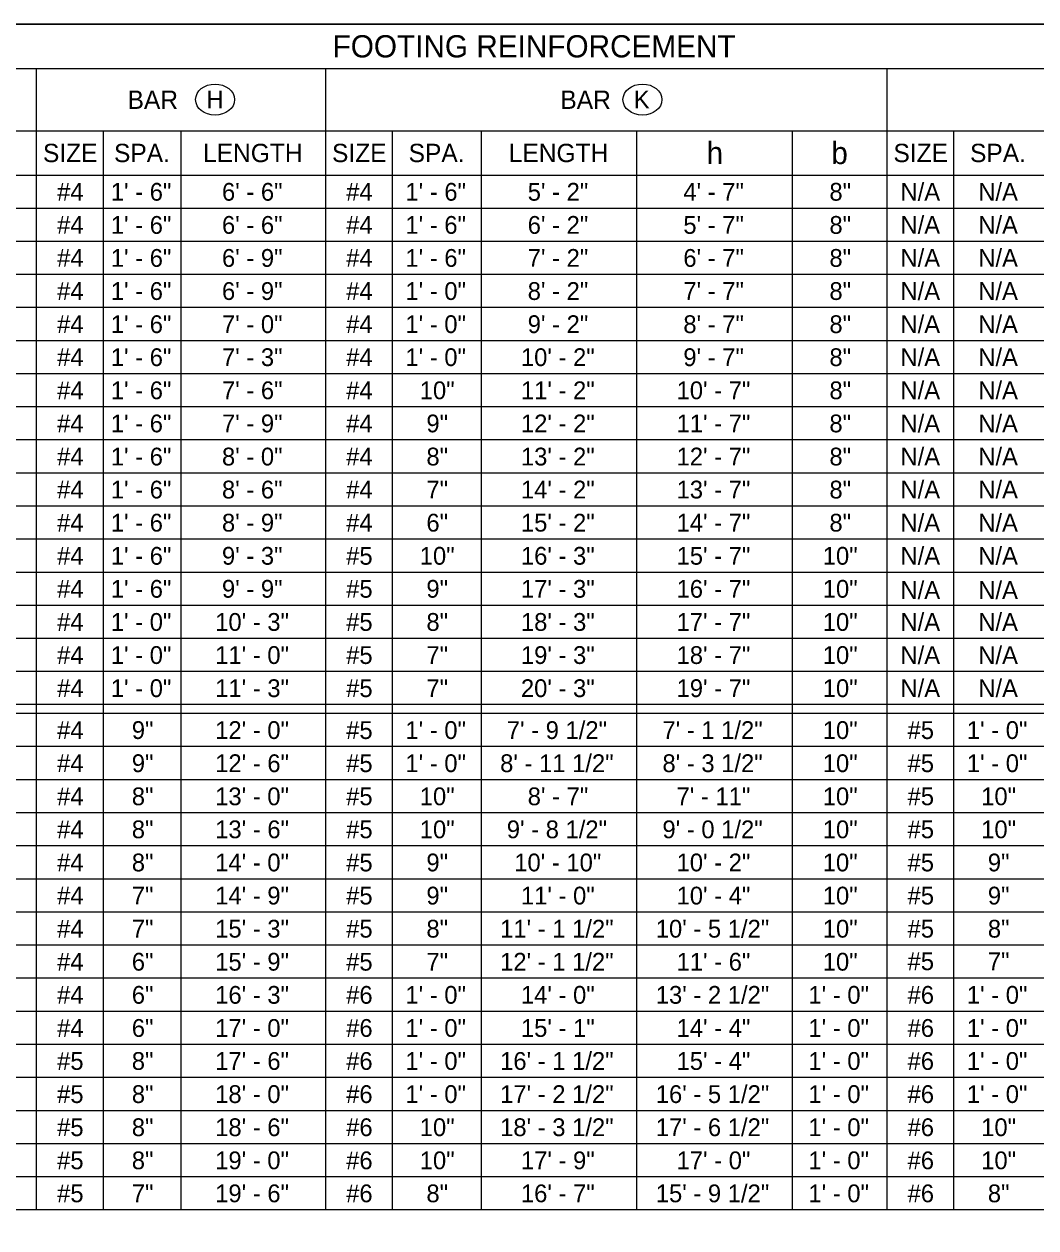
# Model space of a CAD drawing. Extents: x 99862 to 103151, y 100000 to 105076.
# Drawn here: x 100853 to 101763, y 103992 to 105076 of the extents above; entities that cross this region are included whole.
import ezdxf

# ---------------------------------------------------------------- set-up
doc = ezdxf.new("R2010")
doc.units = 0
for name, color, linetype in [('Level 1', 7, 'Continuous'), ('Level 20', 7, 'Continuous'), ('Level 4', 7, 'Continuous')]:
    doc.layers.add(name, color=color, linetype=linetype)

msp = doc.modelspace()

# ---------------------------------------------------------------- linework, layer by layer
at = {"layer": 'Level 1'}
msp.add_lwpolyline([(99862, 102999.5), (103151, 102999.5), (103151, 105075.5), (99862, 105075.5)], close=True, dxfattribs=at)
at = {"layer": 'Level 20'}
for centre in [(101024.5, 105007.5), (101408.9, 105007.5)]:
    msp.add_ellipse(centre, major_axis=(-17.5, 0), ratio=0.8, dxfattribs=at)
at = {"layer": 'Level 4'}
for p, q in [((100404, 105035.5), (102554, 105035.5)), ((100864, 104008.6), (100864, 105035.5)), ((101124, 104008.6), (101124, 105035.5)), ((101629, 104008.6), (101629, 105035.5)), ((100004, 104979.5), (102711, 104979.5)), ((100924, 104008.6), (100924, 104979.5)), ((100994, 104008.6), (100994, 104979.5)), ((101184, 104008.6), (101184, 104979.5)), ((101264, 104008.6), (101264, 104979.5)), ((101404, 104008.6), (101404, 104979.5)), ((101544, 104008.6), (101544, 104979.5)), ((101689, 104008.6), (101689, 104979.5)), ((99929, 104939.5), (103151, 104939.5)), ((103151, 104909.7), (99929, 104909.7)), ((103151, 104880), (99929, 104880)), ((103151, 104850.2), (99929, 104850.2)), ((103151, 104820.4), (99929, 104820.4)), ((103151, 104790.6), (99929, 104790.6)), ((103151, 104760.9), (99929, 104760.9)), ((103151, 104731.1), (99929, 104731.1)), ((103151, 104701.3), (99929, 104701.3)), ((103151, 104671.6), (99929, 104671.6)), ((103151, 104641.8), (99929, 104641.8)), ((103151, 104612), (99929, 104612)), ((103151, 104582.2), (99929, 104582.2)), ((103151, 104552.5), (99929, 104552.5)), ((103151, 104522.7), (99929, 104522.7)), ((103151, 104492.9), (99929, 104492.9)), ((103151, 104463.2), (99929, 104463.2)), ((103151, 104455.2), (99929, 104455.2)), ((103151, 104425.4), (99929, 104425.4)), ((103151, 104395.6), (99929, 104395.6)), ((103151, 104365.8), (99929, 104365.8)), ((103151, 104336.1), (99929, 104336.1)), ((103151, 104306.3), (99929, 104306.3)), ((103151, 104276.5), (99929, 104276.5)), ((103151, 104246.8), (99929, 104246.8)), ((103151, 104217), (99929, 104217)), ((103151, 104187.2), (99929, 104187.2)), ((103151, 104157.4), (99929, 104157.4)), ((103151, 104127.7), (99929, 104127.7)), ((103151, 104097.9), (99929, 104097.9)), ((103151, 104068.1), (99929, 104068.1)), ((103151, 104038.4), (99929, 104038.4))]:
    msp.add_line(p, q, dxfattribs=at)
for points in [[(99929, 105075.5), (103151, 105075.5)], [(103151, 104008.6), (99929, 104008.6), (99929, 105075.5)]]:
    msp.add_lwpolyline(points, dxfattribs=at)

# ---------------------------------------------------------------- texts
at = {"layer": 'Level 20'}
for s, height, p in [('FOOTING REINFORCEMENT', 20, (101130.2, 105045.5)), ('BAR', 16.5, (100945.8, 104999.2)), ('H', 16, (101016.7, 104999.7)), ('BAR', 16.5, (101335.1, 104999.2)), ('K', 16, (101401.1, 104999.7)), ('SIZE', 16.5, (100869.7, 104951.3)), ('SPA.', 16.5, (100933.6, 104951.3)), ('LENGTH', 16.5, (101013.7, 104951.3)), ('SIZE', 16.5, (101129.7, 104951.3)), ('SPA.', 16.5, (101198.6, 104951.3)), ('LENGTH', 16.5, (101288.7, 104951.3)), ('h', 20, (101466.6, 104949.5)), ('b', 20, (101578.8, 104949.5)), ('SIZE', 16.5, (101634.7, 104951.3)), ('SPA.', 16.5, (101703.6, 104951.3))]:
    msp.add_text(s, height=height, dxfattribs=at).set_placement(p)
for p in [(101641, 104916.6), (101711, 104916.6), (101641, 104886.8), (101711, 104886.8), (101641, 104857.1), (101711, 104857.1), (101641, 104827.3), (101711, 104827.3), (101641, 104797.5), (101711, 104797.5), (101641, 104767.8), (101711, 104767.8), (101641, 104738), (101711, 104738), (101641, 104708.2), (101711, 104708.2), (101641, 104678.4), (101711, 104678.4), (101641, 104648.7), (101711, 104648.7), (101641, 104618.9), (101711, 104618.9), (101641, 104589.1), (101711, 104589.1), (101641, 104558.3), (101711, 104558.3), (101641, 104529.6), (101711, 104529.6), (101641, 104499.8), (101711, 104499.8), (101641, 104470), (101711, 104470)]:
    msp.add_text('N/A', height=16, rotation=360, dxfattribs=at).set_placement(p)
at = {"layer": 'Level 4'}
for s, p in [('#4', (100882.4, 104916.6)), ('1\' - 6"', (100930.7, 104916.6)), ('6\' - 6"', (101030.7, 104916.6)), ('#4', (101142.4, 104916.6)), ('1\' - 6"', (101195.7, 104916.6)), ('4\' - 7"', (101445.7, 104916.6)), ('8"', (101577.1, 104916.6)), ('#4', (100882.4, 104886.8)), ('1\' - 6"', (100930.7, 104886.8)), ('6\' - 6"', (101030.7, 104886.8)), ('#4', (101142.4, 104886.8)), ('1\' - 6"', (101195.7, 104886.8)), ('5\' - 7"', (101445.7, 104886.8)), ('8"', (101577.1, 104886.8)), ('#4', (100882.4, 104857.1)), ('1\' - 6"', (100930.7, 104857.1)), ('6\' - 9"', (101030.7, 104857.1)), ('#4', (101142.4, 104857.1)), ('1\' - 6"', (101195.7, 104857.1)), ('6\' - 7"', (101445.7, 104857.1)), ('8"', (101577.1, 104857.1)), ('#4', (100882.4, 104827.3)), ('1\' - 6"', (100930.7, 104827.3)), ('6\' - 9"', (101030.7, 104827.3)), ('#4', (101142.4, 104827.3)), ('1\' - 0"', (101195.7, 104827.3)), ('7\' - 7"', (101445.7, 104827.3)), ('8"', (101577.1, 104827.3)), ('#4', (100882.4, 104797.5)), ('1\' - 6"', (100930.7, 104797.5)), ('7\' - 0"', (101030.7, 104797.5)), ('#4', (101142.4, 104797.5)), ('1\' - 0"', (101195.7, 104797.5)), ('8\' - 7"', (101445.7, 104797.5)), ('8"', (101577.1, 104797.5)), ('#4', (100882.4, 104767.8)), ('1\' - 6"', (100930.7, 104767.8)), ('7\' - 3"', (101030.7, 104767.8)), ('#4', (101142.4, 104767.8)), ('1\' - 0"', (101195.7, 104767.8)), ('9\' - 7"', (101445.7, 104767.8)), ('8"', (101577.1, 104767.8)), ('#4', (100882.4, 104738)), ('1\' - 6"', (100930.7, 104738)), ('7\' - 6"', (101030.7, 104738)), ('#4', (101142.4, 104738)), ('10"', (101208.6, 104738)), ('10\' - 7"', (101439.6, 104738)), ('8"', (101577.1, 104738)), ('#4', (100882.4, 104708.2)), ('1\' - 6"', (100930.7, 104708.2)), ('7\' - 9"', (101030.7, 104708.2)), ('#4', (101142.4, 104708.2)), ('9"', (101214.6, 104708.2)), ('11\' - 7"', (101439.6, 104708.2)), ('8"', (101577.1, 104708.2)), ('#4', (100882.4, 104678.4)), ('1\' - 6"', (100930.7, 104678.4)), ('8\' - 0"', (101030.7, 104678.4)), ('#4', (101142.4, 104678.4)), ('8"', (101214.6, 104678.4)), ('12\' - 7"', (101439.6, 104678.4)), ('8"', (101577.1, 104678.4)), ('#4', (100882.4, 104648.7)), ('1\' - 6"', (100930.7, 104648.7)), ('#4', (101142.4, 104648.7)), ('7"', (101214.6, 104648.7)), ('13\' - 7"', (101439.6, 104648.7)), ('8"', (101577.1, 104648.7)), ('#4', (100882.4, 104618.9)), ('1\' - 6"', (100930.7, 104618.9)), ('#4', (101142.4, 104618.9)), ('6"', (101214.6, 104618.9)), ('14\' - 7"', (101439.6, 104618.9)), ('8"', (101577.1, 104618.9)), ('#4', (100882.4, 104589.1)), ('1\' - 6"', (100930.7, 104589.1)), ('#5', (101142.4, 104589.1)), ('10"', (101208.6, 104589.1)), ('15\' - 7"', (101439.6, 104589.1)), ('#4', (100882.4, 104559.4)), ('1\' - 6"', (100930.7, 104559.4)), ('#5', (101142.4, 104559.4)), ('9"', (101214.6, 104559.4)), ('16\' - 7"', (101439.6, 104559.4)), ('#4', (100882.4, 104529.6)), ('1\' - 0"', (100930.7, 104529.6)), ('#5', (101142.4, 104529.6)), ('8"', (101214.6, 104529.6)), ('17\' - 7"', (101439.6, 104529.6)), ('#4', (100882.4, 104499.8)), ('1\' - 0"', (100930.7, 104499.8)), ('#5', (101142.4, 104499.8)), ('7"', (101214.6, 104499.8)), ('18\' - 7"', (101439.6, 104499.8)), ('#4', (100882.4, 104470)), ('1\' - 0"', (100930.7, 104470)), ('#5', (101142.4, 104470)), ('7"', (101214.6, 104470)), ('19\' - 7"', (101439.6, 104470)), ('#4', (100882.4, 104432.3)), ('9"', (100949.6, 104432.3)), ('#5', (101142.4, 104432.3)), ('1\' - 0"', (101195.7, 104432.3)), ('#5', (101647.4, 104432.3)), ('1\' - 0"', (101700.7, 104432.3)), ('#4', (100882.4, 104402.5)), ('9"', (100949.6, 104402.5)), ('#5', (101142.4, 104402.5)), ('1\' - 0"', (101195.7, 104402.5)), ('#5', (101647.4, 104402.5)), ('1\' - 0"', (101700.7, 104402.5)), ('#4', (100882.4, 104372.7)), ('8"', (100949.6, 104372.7)), ('#5', (101142.4, 104372.7)), ('10"', (101208.6, 104372.7)), ('#5', (101647.4, 104372.7)), ('10"', (101713.6, 104372.7)), ('#4', (100882.4, 104343)), ('8"', (100949.6, 104343)), ('#5', (101142.4, 104343)), ('10"', (101208.6, 104343)), ('#5', (101647.4, 104343)), ('10"', (101713.6, 104343)), ('#4', (100882.4, 104313.2)), ('8"', (100949.6, 104313.2)), ('#5', (101142.4, 104313.2)), ('9"', (101214.6, 104313.2)), ('#5', (101647.4, 104313.2)), ('9"', (101719.6, 104313.2)), ('#4', (100882.4, 104283.4)), ('7"', (100949.6, 104283.4)), ('#5', (101142.4, 104283.4)), ('9"', (101214.6, 104283.4)), ('#5', (101647.4, 104283.4)), ('9"', (101719.6, 104283.4)), ('#4', (100882.4, 104253.6)), ('7"', (100949.6, 104253.6)), ('#5', (101142.4, 104253.6)), ('8"', (101214.6, 104253.6)), ('#5', (101647.4, 104253.6)), ('8"', (101719.6, 104253.6)), ('#4', (100882.4, 104223.9)), ('6"', (100949.6, 104223.9)), ('#5', (101142.4, 104223.9)), ('7"', (101214.6, 104223.9)), ('#5', (101647.4, 104224.3)), ('7"', (101719.6, 104224.3)), ('#4', (100882.4, 104194.1)), ('6"', (100949.6, 104194.1)), ('#6', (101142.4, 104194.1)), ('1\' - 0"', (101195.7, 104194.1)), ('#6', (101647.4, 104194.1)), ('1\' - 0"', (101700.7, 104194.1)), ('#4', (100882.4, 104164.3)), ('6"', (100949.6, 104164.3)), ('#6', (101142.4, 104164.3)), ('1\' - 0"', (101195.7, 104164.3)), ('#6', (101647.4, 104164.3)), ('1\' - 0"', (101700.7, 104164.3)), ('#5', (100882.4, 104134.6)), ('8"', (100949.6, 104134.6)), ('#6', (101142.4, 104134.6)), ('1\' - 0"', (101195.7, 104134.6)), ('#6', (101647.4, 104134.6)), ('1\' - 0"', (101700.7, 104134.6)), ('#5', (100882.4, 104104.8)), ('8"', (100949.6, 104104.8)), ('18\' - 0"', (101024.6, 104104.8)), ('#6', (101142.4, 104104.8)), ('1\' - 0"', (101195.7, 104104.8)), ('#6', (101647.4, 104104.8)), ('1\' - 0"', (101700.7, 104104.8)), ('#5', (100882.4, 104075)), ('8"', (100949.6, 104075)), ('18\' - 6"', (101024.6, 104075)), ('#6', (101142.4, 104075)), ('10"', (101208.6, 104075)), ('#6', (101647.4, 104075)), ('10"', (101713.6, 104075)), ('#5', (100882.4, 104045.2)), ('8"', (100949.6, 104045.2)), ('19\' - 0"', (101024.6, 104045.2)), ('#6', (101142.4, 104045.2)), ('10"', (101208.6, 104045.2)), ('#6', (101647.4, 104045.2)), ('10"', (101713.6, 104045.2)), ('#5', (100882.4, 104015.5)), ('7"', (100949.6, 104015.5)), ('19\' - 6"', (101024.6, 104015.5)), ('#6', (101142.4, 104015.5)), ('8"', (101214.6, 104015.5)), ('#6', (101647.4, 104015.5)), ('8"', (101719.6, 104015.5))]:
    msp.add_text(s, height=16, rotation=360, dxfattribs=at).set_placement(p)
for s, p in [('5\' - 2"', (101305.7, 104916.6)), ('6\' - 2"', (101305.7, 104886.8)), ('7\' - 2"', (101305.7, 104857.1)), ('8\' - 2"', (101305.7, 104827.3)), ('9\' - 2"', (101305.7, 104797.5)), ('10\' - 2"', (101299.6, 104767.8)), ('11\' - 2"', (101299.6, 104738)), ('12\' - 2"', (101299.6, 104708.2)), ('13\' - 2"', (101299.6, 104678.4)), ('8\' - 6"', (101030.7, 104648.7)), ('14\' - 2"', (101299.6, 104648.7)), ('8\' - 9"', (101030.7, 104618.9)), ('15\' - 2"', (101299.6, 104618.9)), ('9\' - 3"', (101030.7, 104589.1)), ('16\' - 3"', (101299.6, 104589.1)), ('10"', (101571.1, 104589.1)), ('9\' - 9"', (101030.7, 104559.4)), ('17\' - 3"', (101299.6, 104559.4)), ('10"', (101571.1, 104559.4)), ('10\' - 3"', (101024.6, 104529.6)), ('18\' - 3"', (101299.6, 104529.6)), ('10"', (101571.1, 104529.6)), ('11\' - 0"', (101024.6, 104499.8)), ('19\' - 3"', (101299.6, 104499.8)), ('10"', (101571.1, 104499.8)), ('11\' - 3"', (101024.6, 104470)), ('20\' - 3"', (101299.6, 104470)), ('10"', (101571.1, 104470)), ('12\' - 0"', (101024.6, 104432.3)), ('7\' - 9 1/2"', (101286.9, 104432.3)), ('7\' - 1 1/2"', (101426.9, 104432.3)), ('10"', (101571.1, 104432.3)), ('12\' - 6"', (101024.6, 104402.5)), ('8\' - 11 1/2"', (101280.9, 104402.5)), ('8\' - 3 1/2"', (101426.9, 104402.5)), ('10"', (101571.1, 104402.5)), ('13\' - 0"', (101024.6, 104372.7)), ('8\' - 7"', (101305.7, 104372.7)), ('7\' - 11"', (101439.6, 104372.7)), ('10"', (101571.1, 104372.7)), ('13\' - 6"', (101024.6, 104343)), ('9\' - 8 1/2"', (101286.9, 104343)), ('9\' - 0 1/2"', (101426.9, 104343)), ('10"', (101571.1, 104343)), ('14\' - 0"', (101024.6, 104313.2)), ('10\' - 10"', (101293.6, 104313.2)), ('10\' - 2"', (101439.6, 104313.2)), ('10"', (101571.1, 104313.2)), ('14\' - 9"', (101024.6, 104283.4)), ('11\' - 0"', (101299.6, 104283.4)), ('10\' - 4"', (101439.6, 104283.4)), ('10"', (101571.1, 104283.4)), ('15\' - 3"', (101024.6, 104253.6)), ('11\' - 1 1/2"', (101280.9, 104253.6)), ('10\' - 5 1/2"', (101420.9, 104253.6)), ('10"', (101571.1, 104253.6)), ('15\' - 9"', (101024.6, 104223.9)), ('12\' - 1 1/2"', (101280.9, 104223.9)), ('11\' - 6"', (101439.6, 104223.9)), ('10"', (101571.1, 104223.9)), ('16\' - 3"', (101024.6, 104194.1)), ('14\' - 0"', (101299.6, 104194.1)), ('13\' - 2 1/2"', (101420.9, 104194.1)), ('1\' - 0"', (101558.2, 104194.1)), ('17\' - 0"', (101024.6, 104164.3)), ('15\' - 1"', (101299.6, 104164.3)), ('14\' - 4"', (101439.6, 104164.3)), ('1\' - 0"', (101558.2, 104164.3)), ('17\' - 6"', (101024.6, 104134.6)), ('16\' - 1 1/2"', (101280.9, 104134.6)), ('15\' - 4"', (101439.6, 104134.6)), ('1\' - 0"', (101558.2, 104134.6)), ('17\' - 2 1/2"', (101280.9, 104104.8)), ('16\' - 5 1/2"', (101420.9, 104104.8)), ('1\' - 0"', (101558.2, 104104.8)), ('18\' - 3 1/2"', (101280.9, 104075)), ('17\' - 6 1/2"', (101420.9, 104075)), ('1\' - 0"', (101558.2, 104075)), ('17\' - 9"', (101299.6, 104045.2)), ('17\' - 0"', (101439.6, 104045.2)), ('1\' - 0"', (101558.2, 104045.2)), ('16\' - 7"', (101299.6, 104015.5)), ('15\' - 9 1/2"', (101420.9, 104015.5)), ('1\' - 0"', (101558.2, 104015.5))]:
    msp.add_text(s, height=16, dxfattribs=at).set_placement(p)

doc.saveas('drawing.dxf')
